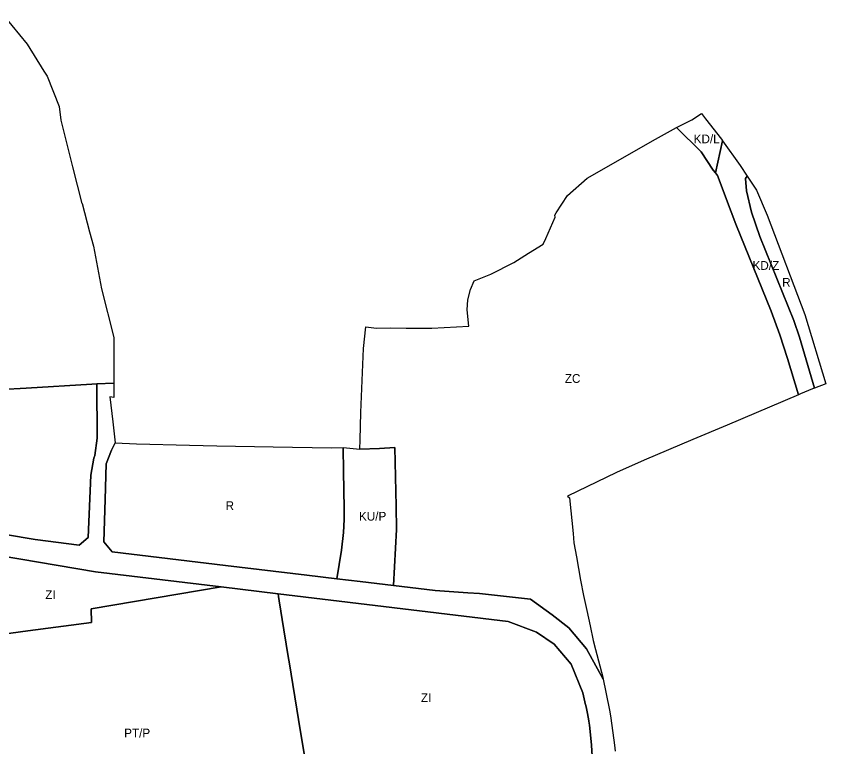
# Model space of a CAD drawing. Extents: x 7436680 to 7439366, y 5548361 to 5550775.
# Drawn here: x 7438434 to 7439358, y 5549471 to 5550305 of the extents above; entities that cross this region are included whole.
import ezdxf

# ---------------------------------------------------------------- set-up
doc = ezdxf.new("R2010")
doc.units = 0
doc.layers.add('linie_rozgraniczajace', color=7, linetype='Continuous')
doc.layers.add('oznaczenia_przeznaczen', color=7, linetype='Continuous')

msp = doc.modelspace()

# ---------------------------------------------------------------- linework, layer by layer
at = {"layer": 'linie_rozgraniczajace'}
for points in [[(7438419.97, 5550305.31), (7438446.34, 5550273.45), (7438465.25, 5550242.41), (7438468.98, 5550236.75), (7438482.61, 5550202.32), (7438484.75, 5550186.67), (7438497.77, 5550133.42), (7438508.68, 5550091.5), (7438509.15, 5550091.54), (7438517.4, 5550059.08), (7438521.86, 5550042.53), (7438531.07, 5549994.14), (7438545.17, 5549938.29), (7438545.06, 5549886.08), (7438525.8, 5549885.33), (7438519.91, 5549885.11), (7438445.23, 5549880.71), (7438388.96, 5549877.4)], [(7438134.5, 5549761.74), (7438455.34, 5549707.81), (7438505.49, 5549701.17), (7438515.84, 5549709.85), (7438519.01, 5549781.08), (7438522.41, 5549800.62), (7438523.38, 5549803.76), (7438526.26, 5549823.31), (7438525.8, 5549885.33), (7438545.06, 5549886.08), (7438545.03, 5549869.81), (7438540.51, 5549870.65), (7438543.96, 5549841.94), (7438546.54, 5549818.05), (7438542.49, 5549809.91), (7438536.54, 5549794.02), (7438535.23, 5549753.49), (7438533.73, 5549704.95), (7438543.35, 5549693.76), (7438672.6, 5549678.22), (7438765.63, 5549667.04), (7438799.85, 5549662.93), (7438826.36, 5549659.74), (7438864.54, 5549655.15), (7438912, 5549649.44), (7438949.03, 5549647.01), (7438962.66, 5549646.13), (7439020.78, 5549639.5), (7439045.43, 5549621.65), (7439064.38, 5549606.89), (7439084.78, 5549582.89), (7439103.88, 5549548.27), (7439106.85, 5549533.52), (7439111.34, 5549511.16), (7439112.35, 5549503.9), (7439116.62, 5549473.09), (7439117.57, 5549466.21)], [(7438388.96, 5549877.4), (7438445.23, 5549880.71), (7438519.91, 5549885.11), (7438525.8, 5549885.33), (7438526.26, 5549823.31), (7438523.38, 5549803.76), (7438522.41, 5549800.62), (7438519.01, 5549781.08), (7438515.84, 5549709.85), (7438505.49, 5549701.17), (7438455.34, 5549707.81), (7438134.5, 5549761.74)], [(7439086.55, 5549505.13), (7439086.47, 5549505.6), (7439086.38, 5549506.08), (7439086.29, 5549506.55), (7439086.21, 5549507.02), (7439086.12, 5549507.49), (7439086.03, 5549507.96), (7439085.94, 5549508.43), (7439085.85, 5549508.9), (7439085.76, 5549509.37), (7439085.66, 5549509.84), (7439085.57, 5549510.31), (7439085.48, 5549510.79), (7439085.38, 5549511.25), (7439085.29, 5549511.73), (7439085.19, 5549512.19), (7439085.09, 5549512.66), (7439085, 5549513.13), (7439084.9, 5549513.6), (7439084.8, 5549514.07), (7439084.7, 5549514.54), (7439084.6, 5549515.01), (7439084.49, 5549515.48), (7439084.39, 5549515.95), (7439084.29, 5549516.42), (7439084.18, 5549516.88), (7439084.08, 5549517.35), (7439083.97, 5549517.82), (7439083.87, 5549518.29), (7439083.76, 5549518.75), (7439083.72, 5549518.93), (7439080.59, 5549532.5), (7439067.23, 5549565.59), (7439047.68, 5549588.29), (7439027.56, 5549601.76), (7438995.42, 5549614.24), (7438732.74, 5549645.81), (7438667.71, 5549653.63), (7438524.19, 5549670.88), (7438393.68, 5549692.83)], [(7438374.79, 5549593.74), (7438447.12, 5549603.43), (7438519.46, 5549613.13), (7438519.25, 5549628.58), (7438667.71, 5549653.63), (7438732.74, 5549645.81), (7438733.23, 5549642.67), (7438734.04, 5549637.73), (7438739.3, 5549604.78), (7438744.56, 5549571.84), (7438745.23, 5549567.95), (7438758.39, 5549488.21), (7438771.55, 5549408.46)], [(7438771.55, 5549408.46), (7438758.39, 5549488.21), (7438745.23, 5549567.95), (7438744.56, 5549571.84), (7438739.3, 5549604.78), (7438734.04, 5549637.73), (7438733.23, 5549642.67), (7438732.74, 5549645.81), (7438995.42, 5549614.24), (7439027.56, 5549601.76), (7439047.68, 5549588.29), (7439067.23, 5549565.59), (7439080.59, 5549532.5), (7439083.72, 5549518.93), (7439083.76, 5549518.75), (7439083.87, 5549518.29), (7439083.97, 5549517.82), (7439084.08, 5549517.35), (7439084.18, 5549516.88), (7439084.29, 5549516.42), (7439084.39, 5549515.95), (7439084.49, 5549515.48), (7439084.6, 5549515.01), (7439084.7, 5549514.54), (7439084.8, 5549514.07), (7439084.9, 5549513.6), (7439085, 5549513.13), (7439085.09, 5549512.66), (7439085.19, 5549512.19), (7439085.29, 5549511.73), (7439085.38, 5549511.25), (7439085.48, 5549510.79), (7439085.57, 5549510.31), (7439085.66, 5549509.84), (7439085.76, 5549509.37), (7439085.85, 5549508.9), (7439085.94, 5549508.43), (7439086.03, 5549507.96), (7439086.12, 5549507.49), (7439086.21, 5549507.02), (7439086.29, 5549506.55), (7439086.38, 5549506.08), (7439086.47, 5549505.6), (7439086.55, 5549505.13), (7439086.64, 5549504.66), (7439086.72, 5549504.19), (7439086.8, 5549503.71), (7439086.88, 5549503.24), (7439086.96, 5549502.77), (7439087.05, 5549502.3), (7439087.13, 5549501.82), (7439087.2, 5549501.35), (7439087.28, 5549500.88), (7439087.36, 5549500.4), (7439087.44, 5549499.93), (7439087.51, 5549499.46), (7439087.59, 5549498.98), (7439087.66, 5549498.51), (7439087.73, 5549498.04), (7439087.81, 5549497.56), (7439087.88, 5549497.09), (7439087.95, 5549496.61), (7439088.02, 5549496.14), (7439088.04, 5549495.99), (7439090.49, 5549472.78), (7439091.28, 5549460.46)], [(7439091.28, 5549460.46), (7439090.49, 5549472.78), (7439088.04, 5549495.99), (7439088.02, 5549496.14), (7439087.95, 5549496.61), (7439087.88, 5549497.09), (7439087.81, 5549497.56), (7439087.73, 5549498.04), (7439087.66, 5549498.51), (7439087.59, 5549498.98), (7439087.51, 5549499.46), (7439087.44, 5549499.93), (7439087.36, 5549500.4), (7439087.28, 5549500.88), (7439087.2, 5549501.35), (7439087.13, 5549501.82), (7439087.05, 5549502.3), (7439086.96, 5549502.77), (7439086.88, 5549503.24), (7439086.8, 5549503.71), (7439086.72, 5549504.19), (7439086.64, 5549504.66), (7439086.55, 5549505.13)]]:
    msp.add_lwpolyline(points, dxfattribs=at)
for points in [[(7439187.46, 5550178.1), (7439205.09, 5550187.04), (7439216.08, 5550194.32), (7439220.44, 5550188.01), (7439238.61, 5550164.93), (7439240, 5550163.01), (7439231.74, 5550126.35), (7439229.43, 5550129.39), (7439215.64, 5550150.37)], [(7438825.84, 5549811.09), (7438826.13, 5549821.42), (7438827.02, 5549852.66), (7438830.01, 5549925.79), (7438832.74, 5549950.47), (7438845.04, 5549948.9), (7438861.36, 5549949.29), (7438878.83, 5549949.14), (7438893.23, 5549949.11), (7438908.08, 5549949.25), (7438950.4, 5549951.18), (7438948.45, 5549969.83), (7438949.09, 5549981.56), (7438952.16, 5549993.13), (7438956.51, 5550003.07), (7438975.53, 5550010.92), (7439001.79, 5550023.9), (7439018.29, 5550034.62), (7439035.22, 5550044.94), (7439038.35, 5550051.48), (7439049.05, 5550075.9), (7439048.57, 5550078.18), (7439050.19, 5550080.7), (7439063.04, 5550100.73), (7439085.53, 5550120.17), (7439163.28, 5550165.05), (7439187.46, 5550178.1), (7439215.64, 5550150.37), (7439229.43, 5550129.39), (7439231.74, 5550126.35), (7439234.05, 5550123.3), (7439249.97, 5550081.82), (7439255.04, 5550067.89), (7439295.36, 5549968.35), (7439305.47, 5549941.54), (7439314.27, 5549914.26), (7439326.48, 5549873), (7439245.31, 5549838.43), (7439206.16, 5549822.04), (7439150.35, 5549798.36), (7439118.75, 5549784.29), (7439063.16, 5549757.38), (7439065.38, 5549755.25), (7439069.27, 5549714.75), (7439070.33, 5549703.87), (7439073.2, 5549688), (7439078.01, 5549661.43), (7439081.17, 5549643.95), (7439084.95, 5549626.61), (7439088.75, 5549609.19), (7439092.39, 5549592.53), (7439095.12, 5549582.15), (7439103.4, 5549550.65), (7439103.88, 5549548.27), (7439084.78, 5549582.89), (7439064.38, 5549606.89), (7439045.43, 5549621.65), (7439020.78, 5549639.5), (7438962.66, 5549646.13), (7438949.03, 5549647.01), (7438912, 5549649.44), (7438864.54, 5549655.15), (7438867.83, 5549719.1), (7438867.52, 5549745.74), (7438866.71, 5549779.21), (7438865.89, 5549812.68), (7438848.54, 5549811.82)], [(7439231.74, 5550126.35), (7439240, 5550163.01), (7439260.27, 5550134.86), (7439268.13, 5550122.73), (7439266.15, 5550119.94), (7439267.14, 5550105.85), (7439272.96, 5550081.55), (7439282.35, 5550053.72), (7439321.28, 5549957.64), (7439327.87, 5549938.79), (7439345.09, 5549880.62), (7439342.69, 5549879.71), (7439328.99, 5549874.07), (7439326.48, 5549873), (7439314.27, 5549914.26), (7439305.47, 5549941.54), (7439295.36, 5549968.35), (7439255.04, 5550067.89), (7439249.97, 5550081.82), (7439234.05, 5550123.3)], [(7439266.15, 5550119.94), (7439268.13, 5550122.73), (7439278.56, 5550106.62), (7439290.92, 5550078.14), (7439333.77, 5549964.62), (7439357.84, 5549885.47), (7439345.09, 5549880.62), (7439327.87, 5549938.79), (7439321.28, 5549957.64), (7439282.35, 5550053.72), (7439272.96, 5550081.55), (7439267.14, 5550105.85)], [(7438533.73, 5549704.95), (7438535.23, 5549753.49), (7438536.54, 5549794.02), (7438542.49, 5549809.91), (7438546.54, 5549818.05), (7438571.06, 5549816.99), (7438631.48, 5549815.54), (7438662.74, 5549814.79), (7438726.99, 5549813.39), (7438793.65, 5549812.56), (7438806.89, 5549812.93), (7438807.28, 5549785.27), (7438807.88, 5549743.27), (7438808.06, 5549730.55), (7438807.36, 5549715.72), (7438804.86, 5549695.73), (7438799.85, 5549662.93), (7438765.63, 5549667.04), (7438672.6, 5549678.22), (7438543.35, 5549693.76)], [(7438799.85, 5549662.93), (7438804.86, 5549695.73), (7438807.36, 5549715.72), (7438808.06, 5549730.55), (7438807.88, 5549743.27), (7438807.28, 5549785.27), (7438806.89, 5549812.93), (7438825.84, 5549811.09), (7438848.54, 5549811.82), (7438865.89, 5549812.68), (7438866.71, 5549779.21), (7438867.52, 5549745.74), (7438867.83, 5549719.1), (7438864.54, 5549655.15), (7438826.36, 5549659.74)], [(7438374.79, 5549593.74), (7438381.45, 5549684.75), (7438393.68, 5549692.83), (7438524.19, 5549670.88), (7438667.71, 5549653.63), (7438519.25, 5549628.58), (7438519.46, 5549613.13), (7438447.12, 5549603.43)]]:
    msp.add_lwpolyline(points, close=True, dxfattribs=at)

# ---------------------------------------------------------------- texts
at = {"layer": 'oznaczenia_przeznaczen'}
for s, p in [('KD/L', (7439207.01, 5550160.21)), ('KD/Z', (7439274.19, 5550015.67)), ('R', (7439307.97, 5549996.4)), ('ZC', (7439059.91, 5549886.6)), ('R', (7438672.7, 5549741.38)), ('KU/P', (7438824.95, 5549729.31)), ('ZI', (7438466.9, 5549639.77)), ('ZI', (7438895.72, 5549522.24)), ('PT/P', (7438556.94, 5549481.74))]:
    msp.add_text(s, height=10, dxfattribs=at).set_placement(p)

doc.saveas('drawing.dxf')
